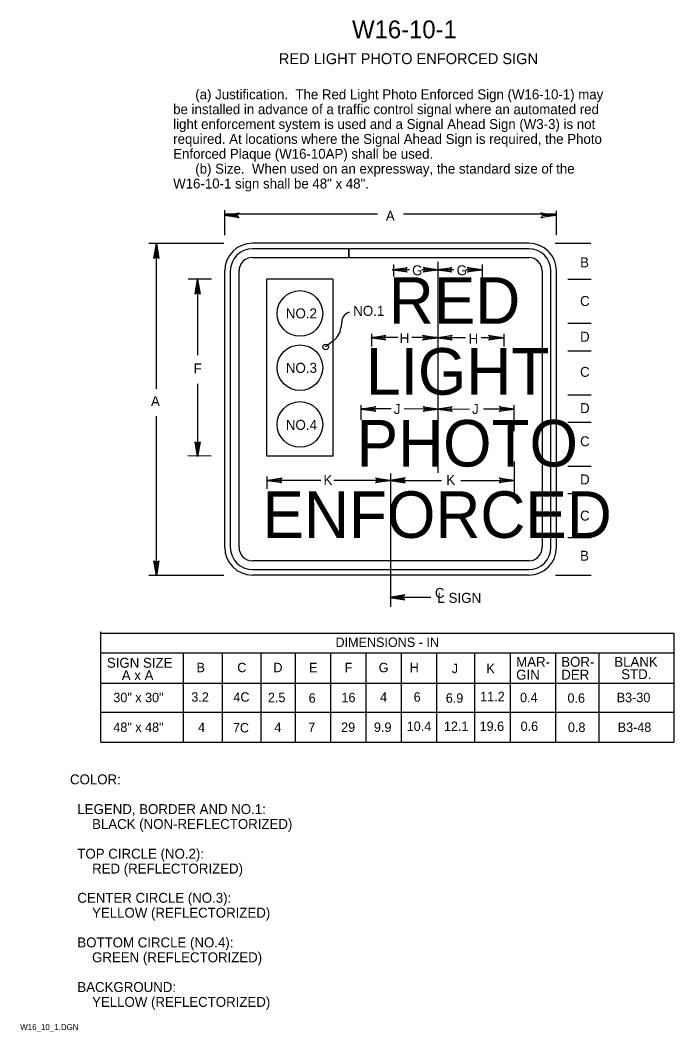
# Model space of a CAD drawing. Extents: x 0.013 to 0.178, y 0.004 to 0.259.
import ezdxf

# ---------------------------------------------------------------- set-up
doc = ezdxf.new("R2010")
doc.units = 0
for name, color, linetype in [('1', 7, 'Continuous'), ('2', 7, 'Continuous'), ('3', 7, 'Continuous')]:
    doc.layers.add(name, color=color, linetype=linetype)

# ---------------------------------------------------------------- blocks, each defined once
blk = doc.blocks.new('RARROW')
at = {"layer": '3'}
for p, q in [((-2.156, 0.28500000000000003), (-2.2665, 0.384625)), ((-2.2665, 0.384625), (0, 0)), ((0, 0), (-2.2665, -0.379125)), ((-2.156, 0.28500000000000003), (-2.075625, 0.12075)), ((0, 0), (-2.156, 0.28500000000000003)), ((-2.14975, -0.2705), (0, 0)), ((-2.075625, 0.12075), (0, 0)), ((0, 0), (-2.074, -0.108)), ((-2.2665, -0.379125), (-2.14975, -0.2705)), ((-2.074, -0.108), (-2.14975, -0.2705))]:
    blk.add_line(p, q, dxfattribs=at)

msp = doc.modelspace()

# ---------------------------------------------------------------- linework, layer by layer
at = {"layer": '1'}
for p, q in [((0.04503730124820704, 0.20282530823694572), (0.06398502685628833, 0.20282530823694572)), ((0.04704816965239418, 0.16608622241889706), (0.04704816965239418, 0.20282530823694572)), ((0.14092826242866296, 0.20282530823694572), (0.07122826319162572, 0.20282530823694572)), ((0.09549452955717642, 0.2014253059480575), (0.07122826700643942, 0.2014253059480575)), ((0.07122826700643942, 0.19922530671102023), (0.09549452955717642, 0.19922530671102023)), ((0.09549452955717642, 0.2014253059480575), (0.09549452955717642, 0.19922530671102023)), ((0.09549452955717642, 0.19922530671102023), (0.09549452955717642, 0.2014253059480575)), ((0.14092826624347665, 0.2014253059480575), (0.09549452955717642, 0.2014253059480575)), ((0.09549452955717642, 0.2014253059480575), (0.09549452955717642, 0.19922530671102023)), ((0.09549452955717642, 0.19922530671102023), (0.14092826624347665, 0.19922530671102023)), ((0.10677826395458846, 0.19745049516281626), (0.10677826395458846, 0.19444719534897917)), ((0.11797826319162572, 0.19814356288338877), (0.11797826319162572, 0.14494430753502)), ((0.12917826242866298, 0.19745049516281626), (0.12917826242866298, 0.1925990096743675)), ((0.06422826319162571, 0.12612530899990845), (0.06422826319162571, 0.19582530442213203)), ((0.06562826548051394, 0.19582530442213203), (0.06562826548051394, 0.12612530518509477)), ((0.06782826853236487, 0.12612530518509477), (0.06782826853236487, 0.19582530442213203)), ((0.1443282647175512, 0.19582530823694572), (0.1443282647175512, 0.12612531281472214)), ((0.14652826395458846, 0.12612531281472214), (0.14652826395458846, 0.19582530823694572)), ((0.14792826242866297, 0.12612530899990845), (0.14792826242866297, 0.19582530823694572)), ((0.057443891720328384, 0.1745746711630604), (0.057443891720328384, 0.19373450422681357)), ((0.07487826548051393, 0.14914317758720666), (0.07487826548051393, 0.19374320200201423)), ((0.09157826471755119, 0.14912596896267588), (0.09157826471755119, 0.19372598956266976)), ((0.09374831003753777, 0.18306206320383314), (0.09354059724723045, 0.1815252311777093)), ((0.10127826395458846, 0.1800103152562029), (0.10127826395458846, 0.17677599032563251)), ((0.134678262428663, 0.1800103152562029), (0.134678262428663, 0.17677599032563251)), ((0.09171866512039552, 0.17829823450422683), (0.08967580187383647, 0.176655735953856)), ((0.057443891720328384, 0.14916114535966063), (0.057443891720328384, 0.167375)), ((0.098678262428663, 0.15829414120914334), (0.098678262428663, 0.16199051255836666)), ((0.13727826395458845, 0.15545585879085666), (0.13727826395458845, 0.16199051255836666)), ((0.14792826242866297, 0.12612530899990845), (0.14792826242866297, 0.16212530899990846)), ((0.04704816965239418, 0.11912530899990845), (0.04704816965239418, 0.1592066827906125)), ((0.13727826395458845, 0.14778258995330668), (0.13727826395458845, 0.1385416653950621)), ((0.07487826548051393, 0.14396864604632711), (0.07487826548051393, 0.14085189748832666)), ((0.10607826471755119, 0.14470792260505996), (0.10607826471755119, 0.11109880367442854)), ((0.14092826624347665, 0.12272531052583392), (0.07122826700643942, 0.12272530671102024)), ((0.07122826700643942, 0.12052530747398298), (0.14092826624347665, 0.12052531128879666)), ((0.04503730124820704, 0.11912530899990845), (0.06398502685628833, 0.11912530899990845)), ((0.14092826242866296, 0.11912530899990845), (0.07122826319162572, 0.11912530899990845))]:
    msp.add_line(p, q, dxfattribs=at)
for centre, radius in [((0.08320528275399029, 0.18510747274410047), 0.005753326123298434), ((0.08320528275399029, 0.1714346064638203), 0.005753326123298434), ((0.08967580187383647, 0.176655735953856), 0.0007035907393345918), ((0.08320528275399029, 0.15711117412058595), 0.005753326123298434)]:
    msp.add_circle(centre, radius, dxfattribs=at)
for centre, radius, start, end in [((0.07122826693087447, 0.1958253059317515), 0.007, 90, 180), ((0.14092826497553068, 0.1958253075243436), 0.007, 0, 90), ((0.07122826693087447, 0.1958253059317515), 0.005599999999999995, 90, 180), ((0.07122826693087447, 0.1958253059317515), 0.003400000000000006, 90, 180), ((0.14092826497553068, 0.1958253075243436), 0.005599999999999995, 0, 90), ((0.14092826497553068, 0.1958253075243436), 0.003400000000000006, 0, 90), ((0.09622879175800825, 0.18299855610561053), 0.002481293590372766, 102.39323079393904, 178.5333926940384), ((0.08858564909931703, 0.18219492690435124), 0.005, 308.7999371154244, 352.3026989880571), ((0.07122826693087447, 0.1261253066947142), 0.007, 180, 270), ((0.07122826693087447, 0.1261253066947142), 0.005599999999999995, 180, 270), ((0.07122826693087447, 0.1261253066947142), 0.003400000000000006, 180, 270), ((0.14092826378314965, 0.12612530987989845), 0.007, 270, 0), ((0.14092826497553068, 0.1261253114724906), 0.005599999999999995, 270, 0), ((0.14092826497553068, 0.1261253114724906), 0.003400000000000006, 270, 0)]:
    msp.add_arc(centre, radius, start, end, dxfattribs=at)
at = {"layer": '3'}
for p, q in [((0.06422826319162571, 0.2048529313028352), (0.06422178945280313, 0.21113510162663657)), ((0.10274425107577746, 0.21011854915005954), (0.06422283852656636, 0.21011854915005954)), ((0.14791352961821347, 0.21011854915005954), (0.10930534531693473, 0.21011854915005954)), ((0.14791885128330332, 0.20495598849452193), (0.14791264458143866, 0.21097863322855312)), ((0.14757821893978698, 0.20282773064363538), (0.15662161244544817, 0.2028370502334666)), ((0.110875, 0.1960813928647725), (0.10677826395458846, 0.1960813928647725)), ((0.11797826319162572, 0.1960813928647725), (0.11398916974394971, 0.1960813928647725)), ((0.122, 0.1960813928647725), (0.11797826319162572, 0.1960813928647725)), ((0.12917826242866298, 0.1960813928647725), (0.12507794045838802, 0.1960813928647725)), ((0.06084850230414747, 0.19373099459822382), (0.05496687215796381, 0.1937370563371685)), ((0.09157826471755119, 0.19372598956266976), (0.07487826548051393, 0.19374320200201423)), ((0.150749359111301, 0.19373099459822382), (0.15663098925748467, 0.1937370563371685)), ((0.15076079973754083, 0.18263100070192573), (0.15664242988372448, 0.18263706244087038)), ((0.10786750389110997, 0.17903919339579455), (0.10127826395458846, 0.17904605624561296)), ((0.11797826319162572, 0.17902866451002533), (0.11139067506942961, 0.17903552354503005)), ((0.11797826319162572, 0.1790275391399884), (0.12500009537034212, 0.17903485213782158)), ((0.12888914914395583, 0.17903890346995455), (0.134678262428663, 0.17904493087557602)), ((0.15076793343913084, 0.17571100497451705), (0.1566495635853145, 0.1757170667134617)), ((0.15077937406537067, 0.16461101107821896), (0.15666100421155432, 0.16461707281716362)), ((0.10625001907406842, 0.1610183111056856), (0.098678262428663, 0.16102619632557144)), ((0.11797826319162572, 0.16100609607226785), (0.1095076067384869, 0.1610149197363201)), ((0.11797826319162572, 0.1610080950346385), (0.12599998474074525, 0.16101644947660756)), ((0.1295477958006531, 0.16102014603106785), (0.13727826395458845, 0.16102819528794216)), ((0.15078650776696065, 0.15769101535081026), (0.15666813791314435, 0.15769707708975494)), ((0.060802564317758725, 0.1491576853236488), (0.054920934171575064, 0.14916374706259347)), ((0.09157826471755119, 0.14912596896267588), (0.07487826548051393, 0.14914317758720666)), ((0.1507979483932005, 0.14659102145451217), (0.15667957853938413, 0.14659708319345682)), ((0.08849999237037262, 0.1429930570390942), (0.07487826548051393, 0.14300724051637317)), ((0.10607826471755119, 0.1429747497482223), (0.09171048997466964, 0.14298971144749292)), ((0.10607826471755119, 0.14297385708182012), (0.11887501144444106, 0.14298718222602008)), ((0.12376286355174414, 0.1429922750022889), (0.13727826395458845, 0.14300634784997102)), ((0.1508050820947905, 0.1396710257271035), (0.15668671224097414, 0.13967708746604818)), ((0.1508165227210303, 0.1285710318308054), (0.15669815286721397, 0.12857709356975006)), ((0.14766447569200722, 0.11913225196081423), (0.15670787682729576, 0.11914157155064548)), ((0.10607826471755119, 0.11357376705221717), (0.11622447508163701, 0.11358433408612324)), ((0.032912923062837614, 0.10482144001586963), (0.032912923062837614, 0.07700577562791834)), ((0.03275, 0.1045), (0.1775, 0.1045)), ((0.17750838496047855, 0.10450577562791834), (0.17750838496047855, 0.07700577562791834)), ((0.17750838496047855, 0.09943665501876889), (0.032912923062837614, 0.09943665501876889)), ((0.05375586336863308, 0.09943665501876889), (0.05375586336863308, 0.07700577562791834)), ((0.0733699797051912, 0.09943665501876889), (0.0733699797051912, 0.07700577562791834)), ((0.1476478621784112, 0.09943665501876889), (0.1476478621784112, 0.07700577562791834)), ((0.15858103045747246, 0.09943665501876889), (0.15858103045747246, 0.07700577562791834)), ((0.033, 0.091875), (0.1775, 0.091875)), ((0.17750838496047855, 0.08443876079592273), (0.032912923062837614, 0.08443876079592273)), ((0.033, 0.077), (0.1775, 0.077))]:
    msp.add_line(p, q, dxfattribs=at)
for points in [[(0.06356292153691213, 0.09943665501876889), (0.06356292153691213, 0.07700577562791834)], [(0.08196292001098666, 0.09943665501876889), (0.08196292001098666, 0.07700577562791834)], [(0.09088791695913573, 0.09943665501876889), (0.09088791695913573, 0.07700577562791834)], [(0.09981291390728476, 0.09943665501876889), (0.09981291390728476, 0.07700577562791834)], [(0.10873791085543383, 0.09943665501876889), (0.10873791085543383, 0.07700577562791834)], [(0.11766290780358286, 0.09943665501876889), (0.11766290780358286, 0.07700577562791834)], [(0.12723791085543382, 0.09943665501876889), (0.12723791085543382, 0.07700577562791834)], [(0.13626290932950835, 0.09943665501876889), (0.13626290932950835, 0.07700577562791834)]]:
    msp.add_lwpolyline(points, dxfattribs=at)

# ---------------------------------------------------------------- block references
for p, xscale, yscale, rotation in [((0.064125, 0.209875), 0.0016545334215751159, 0.0016366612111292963, 179.91708286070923), ((0.14775, 0.209875), 0.0016545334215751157, 0.001636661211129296, -0.08291713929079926), ((0.047, 0.20275), 0.0016545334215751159, 0.0016366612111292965, 90.08291713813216), ((0.1065, 0.196125), 0.0016545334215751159, 0.0016366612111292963, 179.91708286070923), ((0.11800000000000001, 0.196125), 0.0016545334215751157, 0.001636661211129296, -0.08291713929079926), ((0.11775000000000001, 0.196125), 0.0016545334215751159, 0.0016366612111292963, 179.91708286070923), ((0.129125, 0.196125), 0.0016545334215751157, 0.001636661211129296, -0.08291713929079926), ((0.057375, 0.19375), 0.0016545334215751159, 0.0016366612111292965, 90.08291713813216), ((0.101125, 0.179), 0.0016545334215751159, 0.0016366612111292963, 179.91708286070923), ((0.11787500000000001, 0.179), 0.0016545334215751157, 0.001636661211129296, -0.08291713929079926), ((0.11787500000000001, 0.179), 0.0016545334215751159, 0.0016366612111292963, 179.91708286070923), ((0.1345, 0.179), 0.0016545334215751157, 0.001636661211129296, -0.08291713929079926), ((0.098625, 0.161), 0.001654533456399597, 0.0016530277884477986, 179.91625369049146), ((0.11800000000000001, 0.161), 0.0016545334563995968, 0.0016530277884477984, -0.08374630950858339), ((0.11787500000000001, 0.161), 0.001654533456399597, 0.0016530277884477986, 179.91625369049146), ((0.13725, 0.161), 0.0016545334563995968, 0.0016530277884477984, -0.08374630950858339), ((0.057375, 0.149), 0.0016545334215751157, 0.0016366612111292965, -89.91708286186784), ((0.074875, 0.14300000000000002), 0.001654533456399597, 0.0016530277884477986, 179.91625369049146), ((0.106, 0.14300000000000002), 0.0016545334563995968, 0.0016530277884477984, -0.08374630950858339), ((0.106, 0.14300000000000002), 0.0016545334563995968, -0.0016530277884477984, -179.91625369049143), ((0.13725, 0.14300000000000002), 0.0016545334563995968, 0.0016530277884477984, -0.08374630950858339), ((0.047, 0.11900000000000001), 0.0016545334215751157, 0.0016366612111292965, -89.91708286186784), ((0.105875, 0.1135), 0.0016545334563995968, -0.0016530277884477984, -179.91625369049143)]:
    msp.add_blockref('RARROW', p, dxfattribs=dict(at, xscale=xscale, yscale=yscale, rotation=rotation))

# ---------------------------------------------------------------- texts
at = {"layer": '1'}
for s, height, p in [('W16-10-1', 0.0045000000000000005, (0.09635146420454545, 0.2545)), ('RED LIGHT PHOTO ENFORCED SIGN', 0.00275025, (0.077875, 0.248)), ('RED', 0.0117435, (0.105625, 0.1825)), ('LIGHT', 0.0117435, (0.099875, 0.164625)), ('PHOTO', 0.0117435, (0.0975, 0.1465)), ('ENFORCED', 0.0117435, (0.07375, 0.1285)), ('2.5', 0.0023752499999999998, (0.0751213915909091, 0.08706237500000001)), ('6', 0.0023752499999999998, (0.08539706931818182, 0.08693737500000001)), ('16', 0.0023752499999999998, (0.09367729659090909, 0.08706237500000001)), ('6.9', 0.0023752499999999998, (0.11999711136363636, 0.08693737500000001)), ('48" x 48"', 0.0023752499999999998, (0.036120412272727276, 0.079562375)), ('4', 0.0023752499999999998, (0.057510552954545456, 0.079562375)), ('7C', 0.0023752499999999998, (0.06628957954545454, 0.079437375)), ('4', 0.0023752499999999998, (0.07676055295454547, 0.079562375)), ('7', 0.0023752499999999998, (0.08530769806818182, 0.079562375)), ('29', 0.0023752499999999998, (0.09358996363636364, 0.079562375)), ('9.9', 0.0023752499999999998, (0.10187211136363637, 0.079562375)), ('10.4', 0.0023752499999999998, (0.1101372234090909, 0.079812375)), ('12.1', 0.0023752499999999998, (0.11952062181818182, 0.079812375)), ('19.6', 0.0023752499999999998, (0.1285237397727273, 0.079812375)), ('0.6', 0.0023752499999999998, (0.1388685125, 0.079812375)), ('0.8', 0.0023752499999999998, (0.1508060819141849, 0.079562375)), ('B3-48', 0.0023752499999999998, (0.16336346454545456, 0.079562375)), ('COLOR:', 0.0024997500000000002, (0.02519168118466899, 0.06634947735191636)), ('  LEGEND, BORDER AND NO.1:', 0.0024997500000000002, (0.02519168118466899, 0.05884947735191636)), ('      BLACK (NON-REFLECTORIZED)', 0.0024997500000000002, (0.02519168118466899, 0.055099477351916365)), ('  TOP CIRCLE (NO.2):', 0.0024997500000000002, (0.02519168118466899, 0.047599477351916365)), ('      RED (REFLECTORIZED)', 0.0024997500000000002, (0.02519168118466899, 0.04384947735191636)), ('  CENTER CIRCLE (NO.3):', 0.0024997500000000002, (0.02519168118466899, 0.03647447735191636)), ('      YELLOW (REFLECTORIZED)', 0.0024997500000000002, (0.02519168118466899, 0.032724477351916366)), ('  BOTTOM CIRCLE (NO.4):', 0.0024997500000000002, (0.02519168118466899, 0.02522447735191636)), ('      GREEN (REFLECTORIZED)', 0.0024997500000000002, (0.02519168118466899, 0.02147447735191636)), ('  BACKGROUND:', 0.0024997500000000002, (0.02519168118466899, 0.01397447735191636)), ('      YELLOW (REFLECTORIZED)', 0.0024997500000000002, (0.02519168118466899, 0.01022447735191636)), ('W16_10_1.DGN', 0.0015, (0.012625, 0.004375))]:
    msp.add_text(s, height=height, dxfattribs=at).set_placement(p)
at = {"layer": '2'}
for s, p in [('      (a) Justification.  The Red Light Photo Enforced Sign (W16-10-1) may', (0.05122288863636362, 0.23912525)), ('be installed in advance of a traffic control signal where an automated red', (0.05122288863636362, 0.2353755)), ('light enforcement system is used and a Signal Ahead Sign (W3-3) is not', (0.05122288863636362, 0.23162575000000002)), ('required. At locations where the Signal Ahead Sign is required, the Photo', (0.05122288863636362, 0.22787600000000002)), ('Enforced Plaque (W16-10AP) shall be used.', (0.05122288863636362, 0.22412625)), ('      (b) Size.  When used on an expressway, the standard size of the', (0.05122288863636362, 0.2203765)), ('W16-10-1 sign shall be 48" x 48".', (0.05122288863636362, 0.21662675))]:
    msp.add_text(s, height=0.0024997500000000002, dxfattribs=at).set_placement(p)
at = {"layer": '3'}
for s, height, rotation, p in [('A', 0.0024997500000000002, 359.9170833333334, (0.104875, 0.2085)), ('B', 0.0024997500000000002, 359.9170833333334, (0.153875, 0.19675)), ('G', 0.0024997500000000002, 0.08291666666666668, (0.1115, 0.19475)), ('G', 0.0024997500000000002, 0.08291666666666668, (0.12275, 0.19475)), ('C', 0.0024997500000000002, 359.9170833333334, (0.153875, 0.187)), ('NO.2', 0.0025245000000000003, 359.91625555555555, (0.079625, 0.183875)), ('NO.1', 0.0025245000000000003, 0.08374444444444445, (0.096625, 0.1845)), ('H', 0.0024997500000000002, 0.08291666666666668, (0.108375, 0.177625)), ('H', 0.0024997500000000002, 0.08291666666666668, (0.12575, 0.1775)), ('D', 0.0024997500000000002, 0.08291666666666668, (0.153875, 0.178)), ('F', 0.0024997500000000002, 359.9170833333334, (0.056375, 0.17)), ('NO.3', 0.0025245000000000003, 0.08374444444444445, (0.079625, 0.170125)), ('C', 0.0024997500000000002, 0.08291666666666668, (0.153875, 0.169125)), ('A', 0.0024997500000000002, 359.9170833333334, (0.045625, 0.16175)), ('J', 0.0025245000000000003, 359.91625555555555, (0.106875, 0.15975)), ('J', 0.0025245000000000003, 0.08374444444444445, (0.12662500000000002, 0.15975)), ('D', 0.0024997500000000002, 359.9170833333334, (0.153875, 0.16)), ('NO.4', 0.0025245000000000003, 359.91625555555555, (0.079625, 0.15575)), ('C', 0.0024997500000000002, 359.9170833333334, (0.153875, 0.151625)), ('K', 0.0025245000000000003, 359.91625555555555, (0.089125, 0.141875)), ('K', 0.0025245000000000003, 0.08374444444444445, (0.120125, 0.141875)), ('D', 0.0024997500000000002, 0.08291666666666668, (0.153875, 0.14200000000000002)), ('C', 0.0024997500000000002, 359.9170833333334, (0.153875, 0.132875)), ('B', 0.0024997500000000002, 0.08291666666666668, (0.153875, 0.12275)), ('C', 0.0024997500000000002, 0.08291666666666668, (0.11725000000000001, 0.113375)), ('L SIGN', 0.0025245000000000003, 359.91625555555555, (0.11787500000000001, 0.112125))]:
    msp.add_text(s, height=height, rotation=rotation, dxfattribs=at).set_placement(p)
for s, height, p in [('DIMENSIONS - IN', 0.0023752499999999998, (0.09216729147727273, 0.101)), ('SIGN SIZE', 0.0024997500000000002, (0.0345, 0.09575)), ('B', 0.0023752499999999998, (0.057125, 0.094625)), ('C', 0.0023752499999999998, (0.06739385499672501, 0.094625)), ('D', 0.0023752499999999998, (0.0765, 0.094625)), ('E', 0.0023752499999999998, (0.08549959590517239, 0.094625)), ('F', 0.0023752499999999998, (0.09447475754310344, 0.094625)), ('G', 0.0023752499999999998, (0.10306189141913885, 0.094625)), ('H', 0.0023752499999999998, (0.110875, 0.094625)), ('MAR-', 0.0024997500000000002, (0.13775, 0.096)), ('BOR-', 0.0024997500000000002, (0.149125, 0.096)), ('BLANK', 0.0024997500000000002, (0.1625, 0.096)), ('A x A', 0.0024997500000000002, (0.03825, 0.092625)), ('J', 0.0023752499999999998, (0.1215, 0.094375)), ('K', 0.0023752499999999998, (0.13025, 0.094375)), ('GIN', 0.0024997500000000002, (0.13775, 0.09275)), ('DER', 0.0024997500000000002, (0.149125, 0.09275)), ('STD.', 0.0024997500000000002, (0.16425, 0.092875)), ('30" x 30"', 0.0023752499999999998, (0.036120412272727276, 0.08706237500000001)), ('3.2', 0.0023752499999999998, (0.055794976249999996, 0.08718737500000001)), ('4C', 0.0023752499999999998, (0.06641579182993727, 0.08718737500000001)), ('4', 0.0023752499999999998, (0.10342392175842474, 0.08718737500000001)), ('6', 0.0023752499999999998, (0.11189706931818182, 0.08718737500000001)), ('11.2', 0.0023752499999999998, (0.1286661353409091, 0.08731237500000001)), ('0.4', 0.0023752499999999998, (0.13873199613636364, 0.08706237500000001)), ('0.6', 0.0023752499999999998, (0.15069464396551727, 0.08693737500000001)), ('B3-30', 0.0023752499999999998, (0.16312138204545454, 0.08706237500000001))]:
    msp.add_text(s, height=height, dxfattribs=at).set_placement(p)

doc.saveas('drawing.dxf')
